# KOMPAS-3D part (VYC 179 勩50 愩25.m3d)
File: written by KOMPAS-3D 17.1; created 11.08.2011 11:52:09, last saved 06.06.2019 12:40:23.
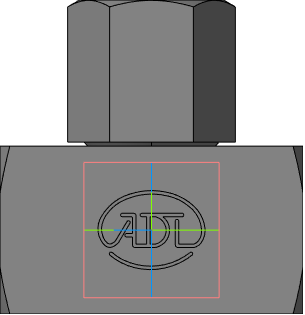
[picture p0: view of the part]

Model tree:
1. Плоскость XY
2. Плоскость ZX
3. Плоскость ZY
4. Ось X
5. Ось Y
6. Ось Z
7. Начало координат
8. Операция без истории:2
